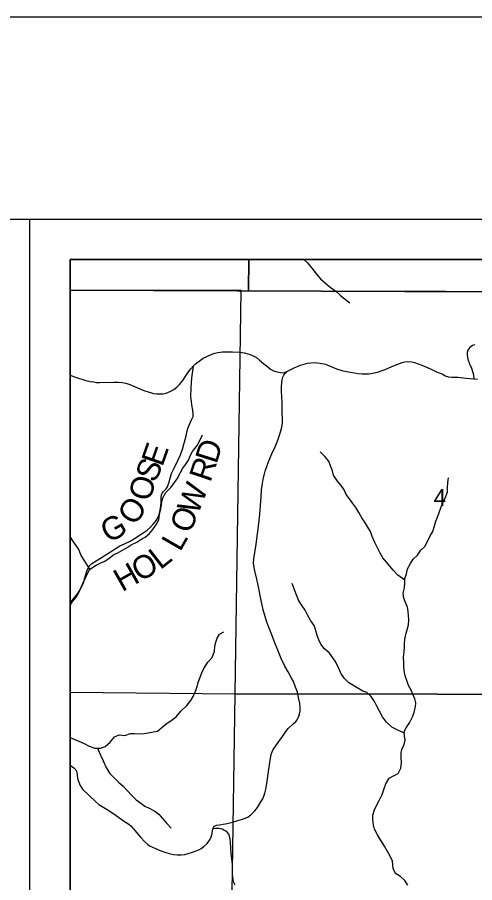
# Model space of a CAD drawing. Extents: x 0 to 34, y -8.9 to 22.
# Drawn here: x 23.586 to 24.719, y 19.856 to 22 of the extents above; entities that cross this region are included whole.
import ezdxf

# ---------------------------------------------------------------- set-up
doc = ezdxf.new("R2010")
doc.units = 0
for name, color, linetype in [('GM_X_Corporation', 7, 'Continuous'), ('GM_X_County_Road', 7, 'Continuous'), ('GM_X_Minor_River', 7, 'Continuous'), ('GM_X_Section_Text', 7, 'Continuous'), ('GM_X_Township_Road', 7, 'Continuous'), ('GM_X_Township_Road_Text', 7, 'Continuous'), ('SH_Border', 7, 'Continuous'), ('SH_Cut_Line', 7, 'Continuous'), ('SH_Data', 7, 'Continuous')]:
    doc.layers.add(name, color=color, linetype=linetype)

msp = doc.modelspace()

# ---------------------------------------------------------------- linework, layer by layer
at = {"layer": 'GM_X_Corporation'}
for points in [[(30.5167, 21.4), (23.7167, 21.4), (23.7167, 19.34), (24.5181, 19.3295), (25.0504, 19.3237), (25.1066, 19.3232), (25.1068, 18.8675), (25.1136, 18.8385), (25.1229, 18.6966), (25.125, 18.6354), (25.1216, 18.6194), (25.1124, 18.5932), (25.1045, 18.3117), (25.2083, 18.3108), (25.7381, 18.312), (26.1399, 18.3037), (26.1391, 17.8847), (26.1361, 17.3278)], [(28.2203, 21.4), (25.1649, 21.4), (25.1646, 21.3656), (25.1645, 21.3632), (25.1639, 21.3208), (25.1355, 21.32), (25.0937, 21.3201), (25.0907, 21.3201), (24.7567, 21.3198), (24.7536, 21.3198), (23.7167, 21.3241), (23.7167, 19.34)]]:
    msp.add_lwpolyline(points, dxfattribs=at)
for points in [[(24.1596, 21.4), (23.7167, 21.4), (23.7167, 21.324), (24.1402, 21.3227), (24.1588, 21.3221)], [(25.1649, 21.4), (23.7167, 21.4), (23.7167, 21.3241), (24.7536, 21.3198), (24.7567, 21.3198), (25.0907, 21.3201), (25.0937, 21.3201), (25.1355, 21.32), (25.1639, 21.3208), (25.1645, 21.3632), (25.1646, 21.3656)], [(25.1653, 21.4), (24.1596, 21.4), (24.1588, 21.3221), (25.1357, 21.3204), (25.1645, 21.3207)], [(23.7167, 21.324), (23.7167, 20.3278), (24.1258, 20.3236), (24.1402, 21.3227)], [(24.1402, 21.3227), (24.1588, 21.3221), (25.1357, 21.3204), (25.1285, 20.3218), (24.1258, 20.3236)], [(25.1285, 20.3218), (25.1197, 19.3292), (24.1109, 19.3387), (24.1258, 20.3236)]]:
    msp.add_lwpolyline(points, close=True, dxfattribs=at)
at = {"layer": 'GM_X_County_Road'}
for points in [[(24.7198, 21.1886), (24.7137, 21.1865), (24.707, 21.1821), (24.7023, 21.175), (24.7007, 21.1692), (24.7006, 21.1634), (24.7025, 21.153), (24.7065, 21.1413), (24.7115, 21.1303), (24.7147, 21.1202), (24.7161, 21.1138), (24.7169, 21.1042), (24.726, 21.1032)], [(24.2549, 21.1228), (24.2719, 21.1312), (24.2874, 21.138), (24.3046, 21.1432), (24.3215, 21.1445), (24.3365, 21.1431), (24.3492, 21.1401), (24.3766, 21.1286), (24.3901, 21.1244), (24.4062, 21.1213), (24.4211, 21.1187), (24.4302, 21.1175), (24.4403, 21.1168), (24.4474, 21.1161), (24.4567, 21.1164), (24.4663, 21.1178), (24.4785, 21.1208), (24.4971, 21.1276), (24.5142, 21.1343), (24.529, 21.1408), (24.5393, 21.1448), (24.5464, 21.1465), (24.5539, 21.1471), (24.5635, 21.1465), (24.5704, 21.1448), (24.5882, 21.138), (24.611, 21.1281), (24.625, 21.1218), (24.6399, 21.1155), (24.6464, 21.1117), (24.6542, 21.1091), (24.6626, 21.1082), (24.6774, 21.108), (24.6981, 21.106), (24.7169, 21.1042)], [(23.7167, 20.1466), (23.7175, 20.146), (23.7256, 20.1399), (23.7304, 20.1348), (23.7332, 20.1294), (23.7351, 20.1149), (23.7367, 20.1085), (23.7396, 20.1003), (23.7425, 20.0948), (23.7447, 20.0913), (23.7475, 20.087), (23.7801, 20.0555), (23.7876, 20.0494), (23.8081, 20.0372), (23.8272, 20.0242), (23.8492, 20.0088), (23.8618, 20.0006), (23.8675, 19.9952), (23.8726, 19.9896), (23.8909, 19.9682), (23.9016, 19.9565), (23.9088, 19.9503), (23.9148, 19.9464), (23.9194, 19.9442), (23.9262, 19.9411), (23.9399, 19.935), (23.951, 19.9311), (23.9624, 19.9275), (23.9725, 19.9256), (23.9822, 19.9246), (23.9921, 19.9245), (24.0006, 19.9254), (24.0095, 19.9275), (24.0196, 19.9311), (24.0268, 19.9333), (24.0355, 19.9368), (24.0414, 19.9403), (24.0481, 19.9453), (24.0559, 19.9529), (24.063, 19.9617), (24.0662, 19.9694), (24.0682, 19.9776), (24.0703, 19.9894), (24.072, 19.9925), (24.0746, 19.9956), (24.0793, 19.9982), (24.087, 19.9991), (24.0957, 20.0003), (24.1056, 20.0023), (24.1192, 20.0059), (24.132, 20.0095), (24.1436, 20.0127), (24.1506, 20.0152), (24.1567, 20.0183), (24.1645, 20.0237), (24.1688, 20.0279), (24.1744, 20.0334), (24.1807, 20.0422), (24.1894, 20.0561), (24.1938, 20.0635), (24.1967, 20.0699), (24.1993, 20.0774), (24.2019, 20.0871), (24.204, 20.1011), (24.2092, 20.137), (24.2132, 20.1637), (24.2152, 20.1732), (24.217, 20.1794), (24.2201, 20.1859), (24.226, 20.1947), (24.234, 20.2055), (24.2431, 20.2182), (24.2497, 20.2281), (24.2539, 20.2338), (24.2571, 20.238), (24.2694, 20.2492), (24.2757, 20.2552), (24.279, 20.2594), (24.2814, 20.2641), (24.2833, 20.2678), (24.2854, 20.273), (24.2867, 20.2803), (24.287, 20.2886), (24.2857, 20.3001), (24.2829, 20.3148), (24.2798, 20.3273), (24.2753, 20.3402), (24.2699, 20.3537), (24.2646, 20.3642), (24.2566, 20.3784), (24.2489, 20.3925), (24.24, 20.411), (24.2344, 20.4238), (24.2222, 20.4543), (24.2161, 20.4697), (24.2081, 20.49), (24.2031, 20.5036), (24.1954, 20.532), (24.1892, 20.5586), (24.1843, 20.5848), (24.1794, 20.608), (24.1742, 20.6285), (24.1724, 20.6369), (24.1709, 20.6473), (24.172, 20.658), (24.1775, 20.6947), (24.1813, 20.7197), (24.1841, 20.746), (24.1868, 20.769), (24.1894, 20.8011), (24.1897, 20.8117), (24.1909, 20.8292), (24.1931, 20.8445), (24.1958, 20.8596), (24.1971, 20.8657), (24.2002, 20.8757), (24.2047, 20.8895), (24.2095, 20.9028), (24.2162, 20.9183), (24.2245, 20.936), (24.2314, 20.9521), (24.2356, 20.9644), (24.2391, 20.9753), (24.2415, 20.984), (24.2432, 20.9952), (24.2431, 21.0069), (24.2425, 21.0194), (24.2419, 21.0315), (24.2417, 21.046), (24.2406, 21.0724), (24.2405, 21.0852), (24.2409, 21.0943), (24.2421, 21.1018), (24.2438, 21.1079), (24.2466, 21.1134), (24.2492, 21.1173), (24.2549, 21.1228)]]:
    msp.add_lwpolyline(points, dxfattribs=at)
at = {"layer": 'GM_X_Minor_River'}
for points in [[(24.2955, 21.4), (24.3052, 21.3917), (24.3155, 21.3781), (24.327, 21.3638), (24.337, 21.3521), (24.3492, 21.3408), (24.3614, 21.331), (24.3751, 21.3213), (24.3862, 21.3115), (24.3961, 21.3032), (24.4095, 21.2923)], [(23.7167, 20.5428), (23.7226, 20.552), (23.732, 20.5642), (23.7387, 20.576), (23.7447, 20.5893), (23.7488, 20.5988), (23.7548, 20.6113), (23.7597, 20.622), (23.7653, 20.6326), (23.7808, 20.6422), (23.7929, 20.6484), (23.8028, 20.6526), (23.813, 20.6599), (23.8251, 20.6691), (23.8349, 20.6729), (23.8467, 20.6794), (23.858, 20.6864), (23.8682, 20.6925), (23.8818, 20.6994), (23.8917, 20.7059), (23.9023, 20.7121), (23.9136, 20.7209), (23.9219, 20.7304), (23.9309, 20.7437), (23.9361, 20.7551), (23.938, 20.768), (23.9402, 20.7775), (23.942, 20.787), (23.9442, 20.7988), (23.946, 20.8094), (23.9535, 20.8228), (23.966, 20.835), (23.9754, 20.8472), (23.9822, 20.8567), (23.99, 20.8723), (23.9961, 20.8826), (24.0036, 20.8925), (24.01, 20.9024), (24.0148, 20.9146), (24.0201, 20.9241), (24.0314, 20.939), (24.0385, 20.9527), (24.0445, 20.9652)], [(24.5459, 20.6052), (24.5286, 20.6175), (24.5168, 20.6303), (24.5053, 20.6443), (24.4919, 20.6609), (24.4846, 20.6718), (24.4781, 20.6854), (24.4719, 20.6983), (24.465, 20.7138), (24.4611, 20.7255), (24.4546, 20.7369), (24.4473, 20.749), (24.4396, 20.7599), (24.4319, 20.7731), (24.425, 20.7849), (24.4173, 20.795), (24.4089, 20.8067), (24.4009, 20.8177), (24.3959, 20.8287), (24.3886, 20.84), (24.3794, 20.8502), (24.3694, 20.8657), (24.3671, 20.8763), (24.362, 20.8888), (24.3574, 20.9005), (24.3482, 20.9114), (24.336, 20.9231)], [(24.5443, 20.428), (24.5454, 20.4397), (24.5453, 20.4492), (24.546, 20.4594), (24.5497, 20.4739), (24.5527, 20.4853), (24.5549, 20.4948), (24.5559, 20.5069), (24.5551, 20.5175), (24.5547, 20.5274), (24.5527, 20.538), (24.5477, 20.5501), (24.5438, 20.5603), (24.5418, 20.5728), (24.5452, 20.5861), (24.5462, 20.599), (24.5458, 20.6096), (24.5502, 20.6207), (24.5524, 20.6332), (24.5603, 20.6465), (24.5667, 20.6572), (24.5773, 20.6671), (24.5859, 20.6797), (24.5957, 20.6889), (24.6036, 20.7041), (24.6092, 20.7147), (24.6156, 20.7258), (24.6197, 20.7402), (24.623, 20.7512), (24.6272, 20.7611), (24.6309, 20.7729), (24.6357, 20.7847), (24.6413, 20.7984), (24.6481, 20.8125), (24.6518, 20.8243), (24.6517, 20.8341), (24.6528, 20.8474), (24.6546, 20.8592)], [(23.7652, 20.6325), (23.7527, 20.6523), (23.7438, 20.6666), (23.7373, 20.6829), (23.7288, 20.6942), (23.7219, 20.7052), (23.7167, 20.7134)], [(24.5447, 20.2257), (24.5239, 20.2359), (24.514, 20.2408), (24.5006, 20.2536), (24.4911, 20.2668), (24.4834, 20.2808), (24.4761, 20.2944), (24.4707, 20.3046), (24.463, 20.3167), (24.4519, 20.3272), (24.442, 20.3302), (24.4279, 20.3381), (24.4169, 20.3448), (24.407, 20.3512), (24.3955, 20.3625), (24.3871, 20.3746), (24.3828, 20.3859), (24.3751, 20.4018), (24.3678, 20.4128), (24.359, 20.4245), (24.3472, 20.4354), (24.3376, 20.4467), (24.3326, 20.4577), (24.3291, 20.4683), (24.3248, 20.4827), (24.3217, 20.4925), (24.3133, 20.5046), (24.3045, 20.5189), (24.2987, 20.531), (24.2918, 20.5412), (24.2822, 20.556), (24.2772, 20.5704), (24.2718, 20.584), (24.2668, 20.5968)], [(23.7167, 20.2152), (23.7168, 20.2151), (23.7286, 20.2103), (23.7385, 20.2065), (23.7511, 20.2005), (23.764, 20.1938), (23.7774, 20.1886), (23.7918, 20.1887), (23.8032, 20.1933), (23.816, 20.2036), (23.8265, 20.2166), (23.8379, 20.222), (23.852, 20.2205), (23.8663, 20.2256), (23.8758, 20.2249), (23.8872, 20.2242), (23.8998, 20.225), (23.91, 20.2266), (23.9229, 20.229), (23.9328, 20.2313), (23.9448, 20.2409), (23.9566, 20.2497), (23.9668, 20.2573), (23.9792, 20.2665), (23.9913, 20.2802), (24.0056, 20.2947), (24.0158, 20.3066), (24.0218, 20.3168), (24.0274, 20.3305), (24.0311, 20.3408), (24.0341, 20.3514), (24.0375, 20.3609), (24.0427, 20.3758), (24.0483, 20.386), (24.0581, 20.4024), (24.0682, 20.4139), (24.0742, 20.4291), (24.0753, 20.4412), (24.0779, 20.4515), (24.0808, 20.4617), (24.0869, 20.4713), (24.0971, 20.4774)], [(24.5538, 19.8496), (24.5461, 19.8613), (24.5351, 19.8711), (24.5232, 19.8782), (24.5171, 19.8911), (24.5158, 19.9085), (24.5097, 19.921), (24.5028, 19.9331), (24.4955, 19.9459), (24.4859, 19.9614), (24.4786, 19.9743), (24.4709, 19.9879), (24.4682, 19.9977), (24.4669, 20.0129), (24.4672, 20.0231), (24.4709, 20.036), (24.4773, 20.0501), (24.4829, 20.0596), (24.4901, 20.0737), (24.4949, 20.0889), (24.499, 20.1003), (24.5076, 20.1144), (24.5182, 20.1202), (24.53, 20.1263), (24.5363, 20.1396), (24.5378, 20.1533), (24.5369, 20.1658), (24.5368, 20.1764), (24.5387, 20.1859), (24.5447, 20.1981), (24.5469, 20.2084), (24.5457, 20.2193), (24.5441, 20.23), (24.5493, 20.2395), (24.558, 20.2517), (24.5659, 20.268), (24.5696, 20.2783), (24.5729, 20.2916), (24.5736, 20.3015), (24.5705, 20.3113), (24.5659, 20.3226), (24.5616, 20.3329), (24.5551, 20.3438), (24.5512, 20.3563), (24.5466, 20.3684), (24.5446, 20.3817), (24.5438, 20.3923), (24.5433, 20.4018), (24.5429, 20.4147), (24.5443, 20.428)], [(23.7842, 20.1886), (23.7927, 20.1697), (23.7988, 20.1572), (23.8058, 20.1413), (23.8138, 20.1266), (23.8272, 20.1134), (23.8372, 20.104), (23.8478, 20.0946), (23.8574, 20.0844), (23.87, 20.0705), (23.88, 20.061), (23.8914, 20.0524), (23.9017, 20.0452), (23.9139, 20.0396), (23.9265, 20.0325), (23.936, 20.0254), (23.9444, 20.0152), (23.9563, 20.0024), (23.9666, 19.9903)]]:
    msp.add_lwpolyline(points, dxfattribs=at)
at = {"layer": 'GM_X_Township_Road'}
for points in [[(24.0226, 21.1366), (24.0276, 21.1412), (24.0393, 21.1503), (24.0466, 21.1552), (24.0552, 21.1597), (24.0674, 21.165), (24.0754, 21.1677), (24.083, 21.1697), (24.0943, 21.1711), (24.1194, 21.1708), (24.1384, 21.1701), (24.1483, 21.1684), (24.1568, 21.1663), (24.1628, 21.1644), (24.1703, 21.1612), (24.1783, 21.1567), (24.1862, 21.1507), (24.1966, 21.1415), (24.2063, 21.1339), (24.2134, 21.1283), (24.2206, 21.1243), (24.2299, 21.1215), (24.2424, 21.119), (24.2475, 21.1197), (24.2549, 21.1228)], [(23.7167, 20.5482), (23.721, 20.5538), (23.7274, 20.5622), (23.7354, 20.572), (23.7429, 20.5846), (23.7493, 20.5987), (23.7533, 20.6107), (23.7582, 20.6278), (23.7617, 20.6365), (23.7657, 20.6419), (23.7706, 20.6461), (23.7921, 20.66), (23.8166, 20.6757), (23.8394, 20.6899), (23.8513, 20.6956), (23.8634, 20.7013), (23.8735, 20.7067), (23.8765, 20.7083), (23.8977, 20.7222), (23.9079, 20.7293), (23.9155, 20.7363), (23.9223, 20.7438), (23.9281, 20.7508), (23.9328, 20.7577), (23.9365, 20.7652), (23.9391, 20.7747), (23.9408, 20.7837), (23.942, 20.7962), (23.9421, 20.8033), (23.9418, 20.8096), (23.9428, 20.8164), (23.9449, 20.8212), (23.9478, 20.8253), (23.9543, 20.8319), (23.9576, 20.8366), (23.9599, 20.8417), (23.9623, 20.8479), (23.9639, 20.8554), (23.968, 20.8696), (23.9711, 20.8759), (23.9755, 20.8843), (23.9835, 20.9014), (23.9902, 20.916), (23.9952, 20.9295), (24.0043, 20.963), (24.0066, 20.9751), (24.0083, 20.9809), (24.0114, 20.9894), (24.0181, 21.004), (24.0212, 21.0111), (24.0219, 21.0177), (24.021, 21.0262), (24.0183, 21.04), (24.017, 21.0476), (24.0161, 21.0594), (24.0168, 21.0827), (24.0185, 21.1069), (24.0203, 21.124), (24.0211, 21.1298), (24.0226, 21.1366)], [(23.7167, 21.1131), (23.7272, 21.109), (23.7556, 21.1003), (23.7661, 21.0975), (23.7749, 21.0963), (23.7818, 21.0953), (23.7899, 21.0949), (23.8248, 21.0961), (23.8354, 21.096), (23.8458, 21.0949), (23.8507, 21.0941), (23.8568, 21.0924), (23.8642, 21.0897), (23.8873, 21.08), (23.8992, 21.0754), (23.91, 21.0715), (23.9234, 21.0681), (23.9308, 21.0671), (23.9386, 21.0666), (23.9469, 21.0671), (23.9543, 21.0686), (23.9607, 21.071), (23.9661, 21.0739), (23.9734, 21.078), (23.9812, 21.0838), (23.9875, 21.0899), (23.9955, 21.0997), (24.0016, 21.1087), (24.01, 21.1218), (24.0154, 21.1293), (24.0226, 21.1366)], [(24.1256, 19.8498), (24.1224, 19.856), (24.1203, 19.8637), (24.119, 19.8746), (24.1189, 19.8912), (24.1192, 19.9002), (24.1173, 19.9148), (24.1159, 19.9288), (24.1141, 19.9551), (24.1136, 19.9637), (24.1119, 19.9707), (24.1101, 19.9754), (24.1062, 19.9796), (24.1022, 19.9829), (24.0975, 19.9861), (24.0934, 19.9882), (24.0854, 19.99), (24.0779, 19.9902), (24.0703, 19.9894)]]:
    msp.add_lwpolyline(points, dxfattribs=at)
at = {"layer": 'SH_Border'}
msp.add_lwpolyline([(1.5, 21.5), (33.5, 21.5), (33.5, 0.5), (1.5, 0.5)], close=True, dxfattribs=at)
at = {"layer": 'SH_Cut_Line'}
msp.add_lwpolyline([(0, 0), (34, 0), (34, 22), (0, 22)], close=True, dxfattribs=at)
at = {"layer": 'SH_Data'}
for points in [[(23.6167, 21.5), (30.6167, 21.5), (30.6167, 14.5), (23.6167, 14.5)], [(23.7167, 21.4), (30.5167, 21.4), (30.5167, 14.6), (23.7167, 14.6)]]:
    msp.add_lwpolyline(points, close=True, dxfattribs=at)

# ---------------------------------------------------------------- texts
at = {"layer": 'GM_X_Section_Text'}
msp.add_text('4', height=0.0419, rotation=0, dxfattribs=at).set_placement((24.6173, 20.7891))
at = {"layer": 'GM_X_Township_Road_Text'}
for s, rotation, p in [('D', 72.5794, (24.0795, 20.8913)), ('E', 70.5783, (23.9452, 20.8844)), ('S', 65.4157, (23.9271, 20.8444)), ('R', 71.2541, (24.064, 20.8457)), ('O', 74.8335, (23.9149, 20.7984)), ('W', 68.5212, (24.0329, 20.7652)), ('O', 53.8359, (23.8756, 20.7377)), ('O', 68.0961, (24.0141, 20.7184)), ('G', 29.0486, (23.8119, 20.6958)), ('L', 60.1092, (23.9891, 20.6738)), ('L', 37.9571, (23.94, 20.6297)), ('O', 29.7471, (23.8892, 20.5999)), ('H', 29.373, (23.8453, 20.5752))]:
    msp.add_text(s, height=0.0568, rotation=rotation, dxfattribs=at).set_placement(p)

doc.saveas('drawing.dxf')
